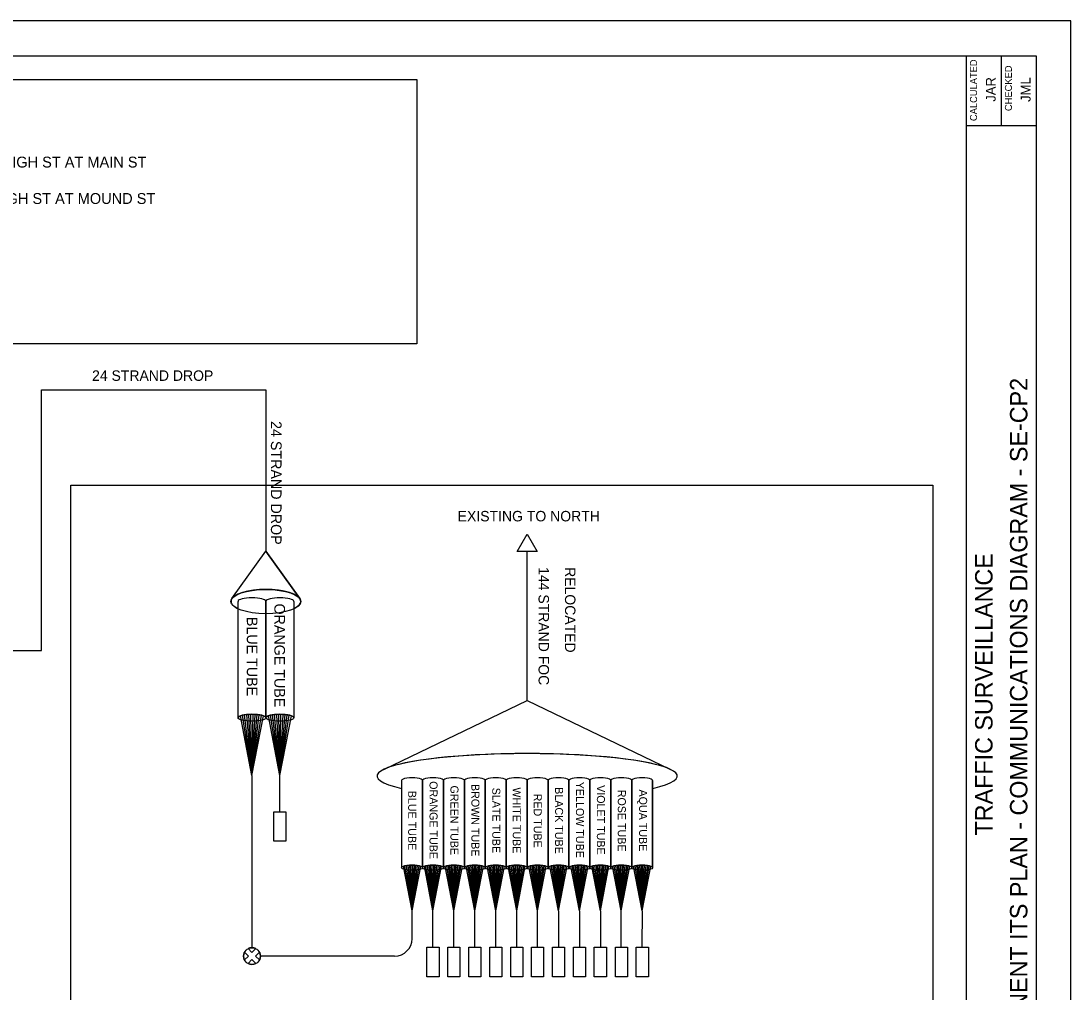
# Model space of a CAD drawing. Extents: x 1805893 to 1833564, y 708898 to 716199.
# Drawn here: x 1831701.4 to 1832002.5, y 713419.3 to 713697.9 of the extents above; entities that cross this region are included whole.
import ezdxf

# ---------------------------------------------------------------- set-up
doc = ezdxf.new("R2010")
doc.units = 0
for name, color, linetype in [('BR_P_Sub_Hidden', 7, 'Continuous'), ('SH_Border', 7, 'Continuous'), ('SH_Cut_Line', 7, 'Continuous'), ('SH_Data', 7, 'Continuous')]:
    doc.layers.add(name, color=color, linetype=linetype)

msp = doc.modelspace()

# ---------------------------------------------------------------- linework, layer by layer
at = {"layer": 'BR_P_Sub_Hidden'}
for points in [[(1831493.37, 713435.11), (1831390.73, 713435.11), (1831390.73, 713681.08), (1831814.91, 713681.08), (1831814.91, 713605.3), (1831695.5, 713605.3), (1831695.5, 713469.79), (1831493.37, 713469.79)], [(1831715.7, 713564.71), (1831962.84, 713564.71), (1831962.84, 713274.41), (1831715.7, 713274.41)]]:
    msp.add_lwpolyline(points, close=True, dxfattribs=at)
at = {"layer": 'SH_Border'}
for p, q in [((1831972.49, 713267.91), (1831972.49, 713687.91)), ((1831982.49, 713687.91), (1831982.49, 713667.91)), ((1831972.49, 713667.91), (1831992.49, 713667.91))]:
    msp.add_line(p, q, dxfattribs=at)
msp.add_lwpolyline([(1831362.49, 713687.91), (1831992.49, 713687.91), (1831992.49, 713267.91), (1831362.49, 713267.91)], close=True, dxfattribs=at)
at = {"layer": 'SH_Cut_Line'}
msp.add_lwpolyline([(1831322.49, 713257.91), (1832002.49, 713257.91), (1832002.49, 713697.91), (1831322.49, 713697.91)], close=True, dxfattribs=at)
at = {"layer": 'SH_Data'}
for p, q in [((1831707.24, 713592.06), (1831771.61, 713592.06)), ((1831707.24, 713517.31), (1831707.24, 713592.06)), ((1831771.61, 713592.06), (1831771.61, 713545.82)), ((1831843.62, 713545.67), (1831846.52, 713550.69)), ((1831846.52, 713550.69), (1831849.41, 713545.67)), ((1831761.88, 713532.23), (1831771.61, 713545.82)), ((1831761.88, 713532.23), (1831771.61, 713545.82)), ((1831781.33, 713532.23), (1831771.61, 713545.82)), ((1831771.61, 713545.82), (1831781.33, 713532.23)), ((1831849.41, 713545.67), (1831843.62, 713545.67)), ((1831846.52, 713502.94), (1831846.52, 713545.67)), ((1831763.61, 713498.01), (1831763.61, 713531.41)), ((1831771.61, 713531.41), (1831771.61, 713498.01)), ((1831771.61, 713498.01), (1831771.61, 713531.41)), ((1831779.61, 713531.41), (1831779.61, 713498.01)), ((1831781.33, 713532.23), (1831781.62, 713531.35)), ((1831677.88, 713517.31), (1831707.24, 713517.31)), ((1831767.61, 713481.45), (1831764.31, 713498.58)), ((1831767.61, 713481.45), (1831764.91, 713498.75)), ((1831767.61, 713481.45), (1831765.51, 713498.86)), ((1831767.61, 713481.45), (1831766.11, 713498.94)), ((1831767.61, 713481.45), (1831766.71, 713498.99)), ((1831767.61, 713481.45), (1831767.31, 713499.01)), ((1831767.61, 713481.45), (1831767.91, 713499.01)), ((1831767.61, 713481.45), (1831768.51, 713498.99)), ((1831767.61, 713481.45), (1831769.11, 713498.94)), ((1831767.61, 713481.45), (1831769.71, 713498.86)), ((1831767.61, 713481.45), (1831770.31, 713498.75)), ((1831767.61, 713481.45), (1831770.91, 713498.58)), ((1831775.61, 713481.45), (1831772.31, 713498.58)), ((1831775.61, 713481.45), (1831772.91, 713498.75)), ((1831775.61, 713481.45), (1831773.51, 713498.86)), ((1831775.61, 713481.45), (1831774.11, 713498.94)), ((1831775.61, 713481.45), (1831774.71, 713498.99)), ((1831775.61, 713481.45), (1831775.31, 713499.01)), ((1831775.61, 713481.45), (1831775.91, 713499.01)), ((1831775.61, 713481.45), (1831776.51, 713498.99)), ((1831775.61, 713481.45), (1831777.11, 713498.94)), ((1831775.61, 713481.45), (1831777.71, 713498.86)), ((1831775.61, 713481.45), (1831778.31, 713498.75)), ((1831775.61, 713481.45), (1831778.91, 713498.58)), ((1831767.61, 713481.45), (1831767.61, 713432.04)), ((1831775.61, 713471.03), (1831775.61, 713481.45)), ((1831810.52, 713480.05), (1831810.52, 713455)), ((1831810.52, 713480.05), (1831810.52, 713455)), ((1831816.52, 713455), (1831816.52, 713480.05)), ((1831816.52, 713480.05), (1831816.52, 713455)), ((1831822.52, 713480.05), (1831822.52, 713455)), ((1831822.52, 713455), (1831822.52, 713480.05)), ((1831828.52, 713455), (1831828.52, 713480.05)), ((1831828.52, 713480.05), (1831828.52, 713455)), ((1831834.52, 713455), (1831834.52, 713480.05)), ((1831834.52, 713480.05), (1831834.52, 713455)), ((1831840.52, 713455), (1831840.52, 713480.05)), ((1831840.52, 713480.05), (1831840.52, 713455)), ((1831846.52, 713455), (1831846.52, 713480.05)), ((1831846.52, 713480.05), (1831846.52, 713455)), ((1831852.52, 713455), (1831852.52, 713480.05)), ((1831852.52, 713480.05), (1831852.52, 713455)), ((1831858.52, 713480.05), (1831858.52, 713455)), ((1831858.52, 713455), (1831858.52, 713480.05)), ((1831864.52, 713455), (1831864.52, 713480.05)), ((1831864.52, 713480.05), (1831864.52, 713455)), ((1831870.52, 713455), (1831870.52, 713480.05)), ((1831870.52, 713480.05), (1831870.52, 713455)), ((1831876.52, 713455), (1831876.52, 713480.05)), ((1831876.52, 713480.05), (1831876.52, 713455)), ((1831882.52, 713455), (1831882.52, 713480.05)), ((1831882.52, 713480.05), (1831882.52, 713455)), ((1831882.52, 713455), (1831882.52, 713477.76)), ((1831813.52, 713442.58), (1831811.04, 713455.42)), ((1831813.52, 713442.58), (1831811.49, 713455.55)), ((1831813.52, 713442.58), (1831811.94, 713455.64)), ((1831813.52, 713442.58), (1831812.39, 713455.69)), ((1831813.52, 713442.58), (1831812.84, 713455.73)), ((1831813.52, 713442.58), (1831813.29, 713455.74)), ((1831813.52, 713442.58), (1831813.74, 713455.74)), ((1831813.52, 713442.58), (1831814.19, 713455.73)), ((1831813.52, 713442.58), (1831814.64, 713455.69)), ((1831813.52, 713442.58), (1831815.09, 713455.64)), ((1831813.52, 713442.58), (1831815.54, 713455.55)), ((1831813.52, 713442.58), (1831815.99, 713455.42)), ((1831819.52, 713442.58), (1831817.04, 713455.42)), ((1831819.52, 713442.58), (1831817.49, 713455.55)), ((1831819.52, 713442.58), (1831817.94, 713455.64)), ((1831819.52, 713442.58), (1831818.39, 713455.69)), ((1831819.52, 713442.58), (1831818.84, 713455.73)), ((1831819.52, 713442.58), (1831819.29, 713455.74)), ((1831819.52, 713442.58), (1831819.74, 713455.74)), ((1831819.52, 713442.58), (1831820.19, 713455.73)), ((1831819.52, 713442.58), (1831820.64, 713455.69)), ((1831819.52, 713442.58), (1831821.09, 713455.64)), ((1831819.52, 713442.58), (1831821.54, 713455.55)), ((1831819.52, 713442.58), (1831821.99, 713455.42)), ((1831825.52, 713442.58), (1831823.04, 713455.42)), ((1831825.52, 713442.58), (1831823.49, 713455.55)), ((1831825.52, 713442.58), (1831823.94, 713455.64)), ((1831825.52, 713442.58), (1831824.39, 713455.69)), ((1831825.52, 713442.58), (1831824.84, 713455.73)), ((1831825.52, 713442.58), (1831825.29, 713455.74)), ((1831825.52, 713442.58), (1831825.74, 713455.74)), ((1831825.52, 713442.58), (1831826.19, 713455.73)), ((1831825.52, 713442.58), (1831826.64, 713455.69)), ((1831825.52, 713442.58), (1831827.09, 713455.64)), ((1831825.52, 713442.58), (1831827.54, 713455.55)), ((1831825.52, 713442.58), (1831827.99, 713455.42)), ((1831831.52, 713442.58), (1831829.04, 713455.42)), ((1831831.52, 713442.58), (1831829.49, 713455.55)), ((1831831.52, 713442.58), (1831829.94, 713455.64)), ((1831831.52, 713442.58), (1831830.39, 713455.69)), ((1831831.52, 713442.58), (1831830.84, 713455.73)), ((1831831.52, 713442.58), (1831831.29, 713455.74)), ((1831831.52, 713442.58), (1831831.74, 713455.74)), ((1831831.52, 713442.58), (1831832.19, 713455.73)), ((1831831.52, 713442.58), (1831832.64, 713455.69)), ((1831831.52, 713442.58), (1831833.09, 713455.64)), ((1831831.52, 713442.58), (1831833.54, 713455.55)), ((1831831.52, 713442.58), (1831833.99, 713455.42)), ((1831837.52, 713442.58), (1831835.04, 713455.42)), ((1831837.52, 713442.58), (1831835.49, 713455.55)), ((1831837.52, 713442.58), (1831835.94, 713455.64)), ((1831837.52, 713442.58), (1831836.39, 713455.69)), ((1831837.52, 713442.58), (1831836.84, 713455.73)), ((1831837.52, 713442.58), (1831837.29, 713455.74)), ((1831837.52, 713442.58), (1831837.74, 713455.74)), ((1831837.52, 713442.58), (1831838.19, 713455.73)), ((1831837.52, 713442.58), (1831838.64, 713455.69)), ((1831837.52, 713442.58), (1831839.09, 713455.64)), ((1831837.52, 713442.58), (1831839.54, 713455.55)), ((1831837.52, 713442.58), (1831839.99, 713455.42)), ((1831843.52, 713442.58), (1831841.04, 713455.42)), ((1831843.52, 713442.58), (1831841.49, 713455.55)), ((1831843.52, 713442.58), (1831841.94, 713455.64)), ((1831843.52, 713442.58), (1831842.39, 713455.69)), ((1831843.52, 713442.58), (1831842.84, 713455.73)), ((1831843.52, 713442.58), (1831843.29, 713455.74)), ((1831843.52, 713442.58), (1831843.74, 713455.74)), ((1831843.52, 713442.58), (1831844.19, 713455.73)), ((1831843.52, 713442.58), (1831844.64, 713455.69)), ((1831843.52, 713442.58), (1831845.09, 713455.64)), ((1831843.52, 713442.58), (1831845.54, 713455.55)), ((1831843.52, 713442.58), (1831845.99, 713455.42)), ((1831849.52, 713442.58), (1831847.04, 713455.42)), ((1831849.52, 713442.58), (1831847.49, 713455.55)), ((1831849.52, 713442.58), (1831847.94, 713455.64)), ((1831849.52, 713442.58), (1831848.39, 713455.69)), ((1831849.52, 713442.58), (1831848.84, 713455.73)), ((1831849.52, 713442.58), (1831849.29, 713455.74)), ((1831849.52, 713442.58), (1831849.74, 713455.74)), ((1831849.52, 713442.58), (1831850.19, 713455.73)), ((1831849.52, 713442.58), (1831850.64, 713455.69)), ((1831849.52, 713442.58), (1831851.09, 713455.64)), ((1831849.52, 713442.58), (1831851.54, 713455.55)), ((1831849.52, 713442.58), (1831851.99, 713455.42)), ((1831855.52, 713442.58), (1831853.04, 713455.42)), ((1831855.52, 713442.58), (1831853.49, 713455.55)), ((1831855.52, 713442.58), (1831853.94, 713455.64)), ((1831855.52, 713442.58), (1831854.39, 713455.69)), ((1831855.52, 713442.58), (1831854.84, 713455.73)), ((1831855.52, 713442.58), (1831855.29, 713455.74)), ((1831855.52, 713442.58), (1831855.74, 713455.74)), ((1831855.52, 713442.58), (1831856.19, 713455.73)), ((1831855.52, 713442.58), (1831856.64, 713455.69)), ((1831855.52, 713442.58), (1831857.09, 713455.64)), ((1831855.52, 713442.58), (1831857.54, 713455.55)), ((1831855.52, 713442.58), (1831857.99, 713455.42)), ((1831861.52, 713442.58), (1831859.04, 713455.42)), ((1831861.52, 713442.58), (1831859.49, 713455.55)), ((1831861.52, 713442.58), (1831859.94, 713455.64)), ((1831861.52, 713442.58), (1831860.39, 713455.69)), ((1831861.52, 713442.58), (1831860.84, 713455.73)), ((1831861.52, 713442.58), (1831861.29, 713455.74)), ((1831861.52, 713442.58), (1831861.74, 713455.74)), ((1831861.52, 713442.58), (1831862.19, 713455.73)), ((1831861.52, 713442.58), (1831862.64, 713455.69)), ((1831861.52, 713442.58), (1831863.09, 713455.64)), ((1831861.52, 713442.58), (1831863.54, 713455.55)), ((1831861.52, 713442.58), (1831863.99, 713455.42)), ((1831867.52, 713442.58), (1831865.04, 713455.42)), ((1831867.52, 713442.58), (1831865.49, 713455.55)), ((1831867.52, 713442.58), (1831865.94, 713455.64)), ((1831867.52, 713442.58), (1831866.39, 713455.69)), ((1831867.52, 713442.58), (1831866.84, 713455.73)), ((1831867.52, 713442.58), (1831867.29, 713455.74)), ((1831867.52, 713442.58), (1831867.74, 713455.74)), ((1831867.52, 713442.58), (1831868.19, 713455.73)), ((1831867.52, 713442.58), (1831868.64, 713455.69)), ((1831867.52, 713442.58), (1831869.09, 713455.64)), ((1831867.52, 713442.58), (1831869.54, 713455.55)), ((1831867.52, 713442.58), (1831869.99, 713455.42)), ((1831873.52, 713442.58), (1831871.04, 713455.42)), ((1831873.52, 713442.58), (1831871.49, 713455.55)), ((1831873.52, 713442.58), (1831871.94, 713455.64)), ((1831873.52, 713442.58), (1831872.39, 713455.69)), ((1831873.52, 713442.58), (1831872.84, 713455.73)), ((1831873.52, 713442.58), (1831873.29, 713455.74)), ((1831873.52, 713442.58), (1831873.74, 713455.74)), ((1831873.52, 713442.58), (1831874.19, 713455.73)), ((1831873.52, 713442.58), (1831874.64, 713455.69)), ((1831873.52, 713442.58), (1831875.09, 713455.64)), ((1831873.52, 713442.58), (1831875.54, 713455.55)), ((1831873.52, 713442.58), (1831875.99, 713455.42)), ((1831879.52, 713442.58), (1831877.04, 713455.42)), ((1831879.52, 713442.58), (1831877.49, 713455.55)), ((1831879.52, 713442.58), (1831877.94, 713455.64)), ((1831879.52, 713442.58), (1831878.39, 713455.69)), ((1831879.52, 713442.58), (1831878.84, 713455.73)), ((1831879.52, 713442.58), (1831879.29, 713455.74)), ((1831879.52, 713442.58), (1831879.74, 713455.74)), ((1831879.52, 713442.58), (1831880.19, 713455.73)), ((1831879.52, 713442.58), (1831880.64, 713455.69)), ((1831879.52, 713442.58), (1831881.09, 713455.64)), ((1831879.52, 713442.58), (1831881.54, 713455.55)), ((1831879.52, 713442.58), (1831881.99, 713455.42)), ((1831813.52, 713434.63), (1831813.52, 713442.58)), ((1831819.52, 713432.16), (1831819.52, 713442.58)), ((1831825.52, 713432.16), (1831825.52, 713442.58)), ((1831831.52, 713432.16), (1831831.52, 713442.58)), ((1831837.52, 713432.16), (1831837.52, 713442.58)), ((1831843.55, 713432.16), (1831843.56, 713442.58)), ((1831849.52, 713432.16), (1831849.52, 713442.58)), ((1831855.52, 713442.58), (1831855.52, 713432.16)), ((1831861.52, 713442.58), (1831861.52, 713432.16)), ((1831867.52, 713442.58), (1831867.52, 713432.16)), ((1831873.52, 713432.16), (1831873.52, 713442.58)), ((1831879.55, 713432.16), (1831879.56, 713442.58)), ((1831766.59, 713429.63), (1831765.47, 713430.75)), ((1831765.47, 713430.75), (1831766.59, 713429.63)), ((1831767.61, 713430.65), (1831766.49, 713431.77)), ((1831767.61, 713430.65), (1831766.49, 713431.77)), ((1831767.61, 713430.65), (1831768.73, 713431.77)), ((1831768.73, 713431.77), (1831767.61, 713430.65)), ((1831768.63, 713429.63), (1831769.74, 713430.75)), ((1831768.63, 713429.63), (1831769.74, 713430.75)), ((1831765.47, 713428.51), (1831766.59, 713429.63)), ((1831766.59, 713429.63), (1831765.47, 713428.51)), ((1831766.49, 713427.49), (1831767.61, 713428.61)), ((1831766.49, 713427.49), (1831767.61, 713428.61)), ((1831768.73, 713427.49), (1831767.61, 713428.61)), ((1831767.61, 713428.61), (1831768.73, 713427.49)), ((1831769.74, 713428.51), (1831768.63, 713429.63)), ((1831769.74, 713428.51), (1831768.63, 713429.63)), ((1831808.52, 713429.63), (1831770.02, 713429.63))]:
    msp.add_line(p, q, dxfattribs=at)
msp.add_lwpolyline([(1831805.42, 713483.21), (1831846.52, 713502.94), (1831887.61, 713483.21)], dxfattribs=at)
msp.add_lwpolyline([(1831805.42, 713483.21), (1831846.52, 713502.94), (1831887.61, 713483.21)], dxfattribs=at)
for points in [[(1831777.34, 713462.59), (1831773.88, 713462.59), (1831773.88, 713471.03), (1831777.34, 713471.03)], [(1831821.25, 713423.71), (1831817.79, 713423.71), (1831817.79, 713432.16), (1831821.25, 713432.16)], [(1831827.25, 713423.71), (1831823.79, 713423.71), (1831823.79, 713432.16), (1831827.25, 713432.16)], [(1831833.25, 713423.71), (1831829.79, 713423.71), (1831829.79, 713432.16), (1831833.25, 713432.16)], [(1831839.28, 713423.71), (1831835.82, 713423.71), (1831835.82, 713432.16), (1831839.28, 713432.16)], [(1831845.28, 713423.71), (1831841.82, 713423.71), (1831841.82, 713432.16), (1831845.28, 713432.16)], [(1831851.25, 713423.71), (1831847.79, 713423.71), (1831847.79, 713432.16), (1831851.25, 713432.16)], [(1831857.25, 713423.71), (1831853.79, 713423.71), (1831853.79, 713432.16), (1831857.25, 713432.16)], [(1831863.25, 713423.71), (1831859.79, 713423.71), (1831859.79, 713432.16), (1831863.25, 713432.16)], [(1831869.25, 713423.71), (1831865.79, 713423.71), (1831865.79, 713432.16), (1831869.25, 713432.16)], [(1831875.28, 713423.71), (1831871.82, 713423.71), (1831871.82, 713432.16), (1831875.28, 713432.16)], [(1831881.28, 713423.71), (1831877.82, 713423.71), (1831877.82, 713432.16), (1831881.28, 713432.16)]]:
    msp.add_lwpolyline(points, close=True, dxfattribs=at)
msp.add_circle((1831767.61, 713429.63), 2.41, dxfattribs=at)
for centre, radius, start, end in [((1831808.52, 713434.63), 5, 270, 0), ((1831767.61, 713429.63), 2.41, 152.353, 207.647), ((1831767.61, 713429.63), 2.41, 62.353, 117.647), ((1831767.61, 713429.63), 2.41, 332.353, 27.647), ((1831767.61, 713429.63), 2.41, 242.353, 297.647)]:
    msp.add_arc(centre, radius, start, end, dxfattribs=at)
for centre, major_axis, ratio, start_param, end_param in [((1831771.61, 713531.41), (10.01, 0), 0.341831, 5.638089, 10.069875), ((1831771.61, 713531.41), (10.01, 0), 0.341831, 6.265717, 9.184951), ((1831767.61, 713531.41), (-4, 0), 0.25, 3.141593, 6.283185), ((1831775.61, 713531.41), (-4, 0), 0.25, 3.141593, 6.283185), ((1831767.61, 713498.01), (-4, 0), 0.25, 3.141593, 6.283185), ((1831775.61, 713498.01), (-4, 0), 0.25, 3.141593, 6.283185), ((1831846.52, 713481.29), (43.05, 0), 0.149566, 5.702888, 10.005075), ((1831846.52, 713481.29), (43.05, 0), 0.149566, 5.702888, 10.005075), ((1831846.52, 713481.29), (43.05, 0), 0.149566, 0.302036, 2.839557), ((1831813.52, 713480.05), (3, 0), 0.25, 0, 3.141593), ((1831813.52, 713480.05), (3, 0), 0.25, 0, 3.141593), ((1831819.52, 713480.05), (3, 0), 0.25, 0, 3.141593), ((1831819.52, 713480.05), (3, 0), 0.25, 0, 3.141593), ((1831825.52, 713480.05), (3, 0), 0.25, 0, 3.141593), ((1831825.52, 713480.05), (3, 0), 0.25, 0, 3.141593), ((1831831.52, 713480.05), (3, 0), 0.25, 0, 3.141593), ((1831831.52, 713480.05), (3, 0), 0.25, 0, 3.141593), ((1831837.52, 713480.05), (3, 0), 0.25, 0, 3.141593), ((1831837.52, 713480.05), (3, 0), 0.25, 0, 3.141593), ((1831843.52, 713480.05), (3, 0), 0.25, 0, 3.141593), ((1831843.52, 713480.05), (3, 0), 0.25, 0, 3.141593), ((1831849.52, 713480.05), (3, 0), 0.25, 0, 3.141593), ((1831849.52, 713480.05), (3, 0), 0.25, 0, 3.141593), ((1831855.52, 713480.05), (3, 0), 0.25, 0, 3.141593), ((1831855.52, 713480.05), (3, 0), 0.25, 0, 3.141593), ((1831861.52, 713480.05), (3, 0), 0.25, 0, 3.141593), ((1831861.52, 713480.05), (3, 0), 0.25, 0, 3.141593), ((1831867.52, 713480.05), (3, 0), 0.25, 0, 3.141593), ((1831867.52, 713480.05), (3, 0), 0.25, 0, 3.141593), ((1831873.52, 713480.05), (3, 0), 0.25, 0, 3.141593), ((1831873.52, 713480.05), (3, 0), 0.25, 0, 3.141593), ((1831879.52, 713480.05), (3, 0), 0.25, 0, 3.141593), ((1831879.52, 713480.05), (3, 0), 0.25, 0, 3.141593), ((1831813.52, 713455), (3, 0), 0.25, 0, 3.141593), ((1831819.52, 713455), (3, 0), 0.25, 0, 3.141593), ((1831825.52, 713455), (3, 0), 0.25, 0, 3.141593), ((1831831.52, 713455), (3, 0), 0.25, 0, 3.141593), ((1831837.52, 713455), (3, 0), 0.25, 0, 3.141593), ((1831843.52, 713455), (3, 0), 0.25, 0, 3.141593), ((1831849.52, 713455), (3, 0), 0.25, 0, 3.141593), ((1831855.52, 713455), (3, 0), 0.25, 0, 3.141593), ((1831861.52, 713455), (3, 0), 0.25, 0, 3.141593), ((1831867.52, 713455), (3, 0), 0.25, 0, 3.141593), ((1831873.52, 713455), (3, 0), 0.25, 0, 3.141593), ((1831879.52, 713455), (3, 0), 0.25, 0, 3.141593)]:
    msp.add_ellipse(centre, major_axis=major_axis, ratio=ratio, start_param=start_param, end_param=end_param, dxfattribs=at)
for centre, major_axis, ratio in [((1831771.6, 713531.35), (-10.02, 0), 0.347607), ((1831767.61, 713498.01), (-4, 0), 0.25), ((1831775.61, 713498.01), (-4, 0), 0.25), ((1831813.52, 713455), (3, 0), 0.25), ((1831819.52, 713455), (3, 0), 0.25), ((1831825.52, 713455), (3, 0), 0.25), ((1831831.52, 713455), (3, 0), 0.25), ((1831837.52, 713455), (3, 0), 0.25), ((1831843.52, 713455), (3, 0), 0.25), ((1831849.52, 713455), (3, 0), 0.25), ((1831855.52, 713455), (3, 0), 0.25), ((1831861.52, 713455), (3, 0), 0.25), ((1831867.52, 713455), (3, 0), 0.25), ((1831873.52, 713455), (3, 0), 0.25), ((1831879.52, 713455), (3, 0), 0.25)]:
    msp.add_ellipse(centre, major_axis=major_axis, ratio=ratio, dxfattribs=at)

# ---------------------------------------------------------------- texts
for s, height, rotation, p in [('CALCULATED', 2, 90, (1831975.54, 713669.2)), ('CHECKED', 2, 90, (1831985.54, 713672.07)), ('JAR', 2.8, 90, (1831980.89, 713674.74)), ('JML', 2.8, 90, (1831990.89, 713674.7)), ('24 STRAND DROP', 3, 360, (1831721.75, 713594.67)), ('PERMANENT ITS PLAN - COMMUNICATIONS DIAGRAM - SE-CP2', 5, 90, (1831989.99, 713390.45)), ('24 STRAND DROP', 3.0596, 270, (1831773.04, 713583.12)), ('EXISTING TO NORTH', 3, 360, (1831826.6, 713554.35)), ('TRAFFIC SURVEILLANCE', 5, 90, (1831979.99, 713464.23)), ('144 STRAND FOC', 3, 270, (1831849.79, 713541.22)), ('RELOCATED', 3, 270, (1831857.37, 713541.22)), ('ORANGE TUBE', 3.0596, 270, (1831774.02, 713530.79)), ('BLUE TUBE', 3.06, 270, (1831766.13, 713526.95)), ('ORANGE TUBE', 2.2947, 270, (1831818.53, 713479.81)), ('YELLOW TUBE', 2.2947, 270, (1831860.53, 713479.63)), ('BLUE TUBE', 2.295, 270, (1831812.41, 713477.05)), ('GREEN TUBE', 2.295, 270, (1831824.53, 713478.57)), ('BROWN TUBE', 2.295, 270, (1831830.53, 713479.01)), ('SLATE TUBE', 2.295, 270, (1831836.53, 713477.94)), ('WHITE TUBE', 2.295, 270, (1831842.41, 713478.03)), ('RED TUBE', 2.295, 270, (1831848.41, 713476.24)), ('BLACK TUBE', 2.295, 270, (1831854.53, 713478.08)), ('VIOLET TUBE', 2.2947, 270, (1831866.53, 713478.68)), ('ROSE TUBE', 2.295, 270, (1831872.53, 713477.35)), ('AQUA TUBE', 2.295, 270, (1831878.63, 713477.43))]:
    msp.add_text(s, height=height, rotation=rotation, dxfattribs=at).set_placement(p)
for s, p in [('PORT 9:            CONNECTION TO INT# 0075: S HIGH ST AT MAIN ST', (1831603.8, 713655.87)), ('PORT 10:           CONNECTION TO INT# 0083: HIGH ST AT MOUND ST', (1831603.8, 713645.42))]:
    msp.add_text(s, height=3.1201, dxfattribs=at).set_placement(p)

doc.saveas('drawing.dxf')
